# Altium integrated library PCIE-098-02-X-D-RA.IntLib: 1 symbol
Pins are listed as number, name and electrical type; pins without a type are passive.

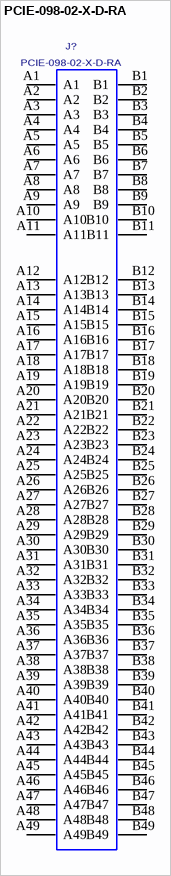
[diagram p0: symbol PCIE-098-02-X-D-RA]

## PCIE-098-02-X-D-RA
designator J?
PCI EXPRESS RIGHT ANGLE ASSEMBLY, 98 PINS.; MANUFACTURER: SAMTEC
footprint PCIE-098-02-X-D-RA
pins: A1, A2, A3, A4, A5, A6, A7, A8, A9, A10, A11, A12, A13, A14, A15, A16, A17, A18, A19, A20, A21, A22, A23, A24, A25, A26, A27, A28, A29, A30, A31, A32, A33, A34, A35, A36, A37, A38, A39, A40, A41, A42, A43, A44, A45, A46, A47, A48, A49, B1, B2, B3, B4, B5, B6, B7, B8, B9, B10, B11, B12, B13, B14, B15, B16, B17, B18, B19, B20, B21, B22, B23, B24, B25, B26, B27, B28, B29, B30, B31, B32, B33, B34, B35, B36, B37, B38, B39, B40, B41, B42, B43, B44, B45, B46, B47, B48, B49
